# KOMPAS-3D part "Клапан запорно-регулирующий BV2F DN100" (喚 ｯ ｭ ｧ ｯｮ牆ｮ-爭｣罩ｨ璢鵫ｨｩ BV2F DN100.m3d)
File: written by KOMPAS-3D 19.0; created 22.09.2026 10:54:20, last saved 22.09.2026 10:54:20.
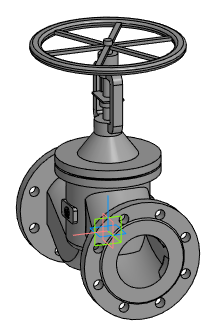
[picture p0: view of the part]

Document properties: Автор: Энергия; Полное имя файла: Z:\3.Личные\sachek\Dendor\_3D для проектировщиков\5.7 Клапан запорно-регулирующий BV2F\BV2F_STP\Клапан запорно-регулирующий BV2F DN100.m3d

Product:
- Part/product: Клапан запорно-регулирующий BV2F DN100

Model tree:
1. Операция без истории:1  (labels: Клапан запорно-регулирующий BV2F DN100)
